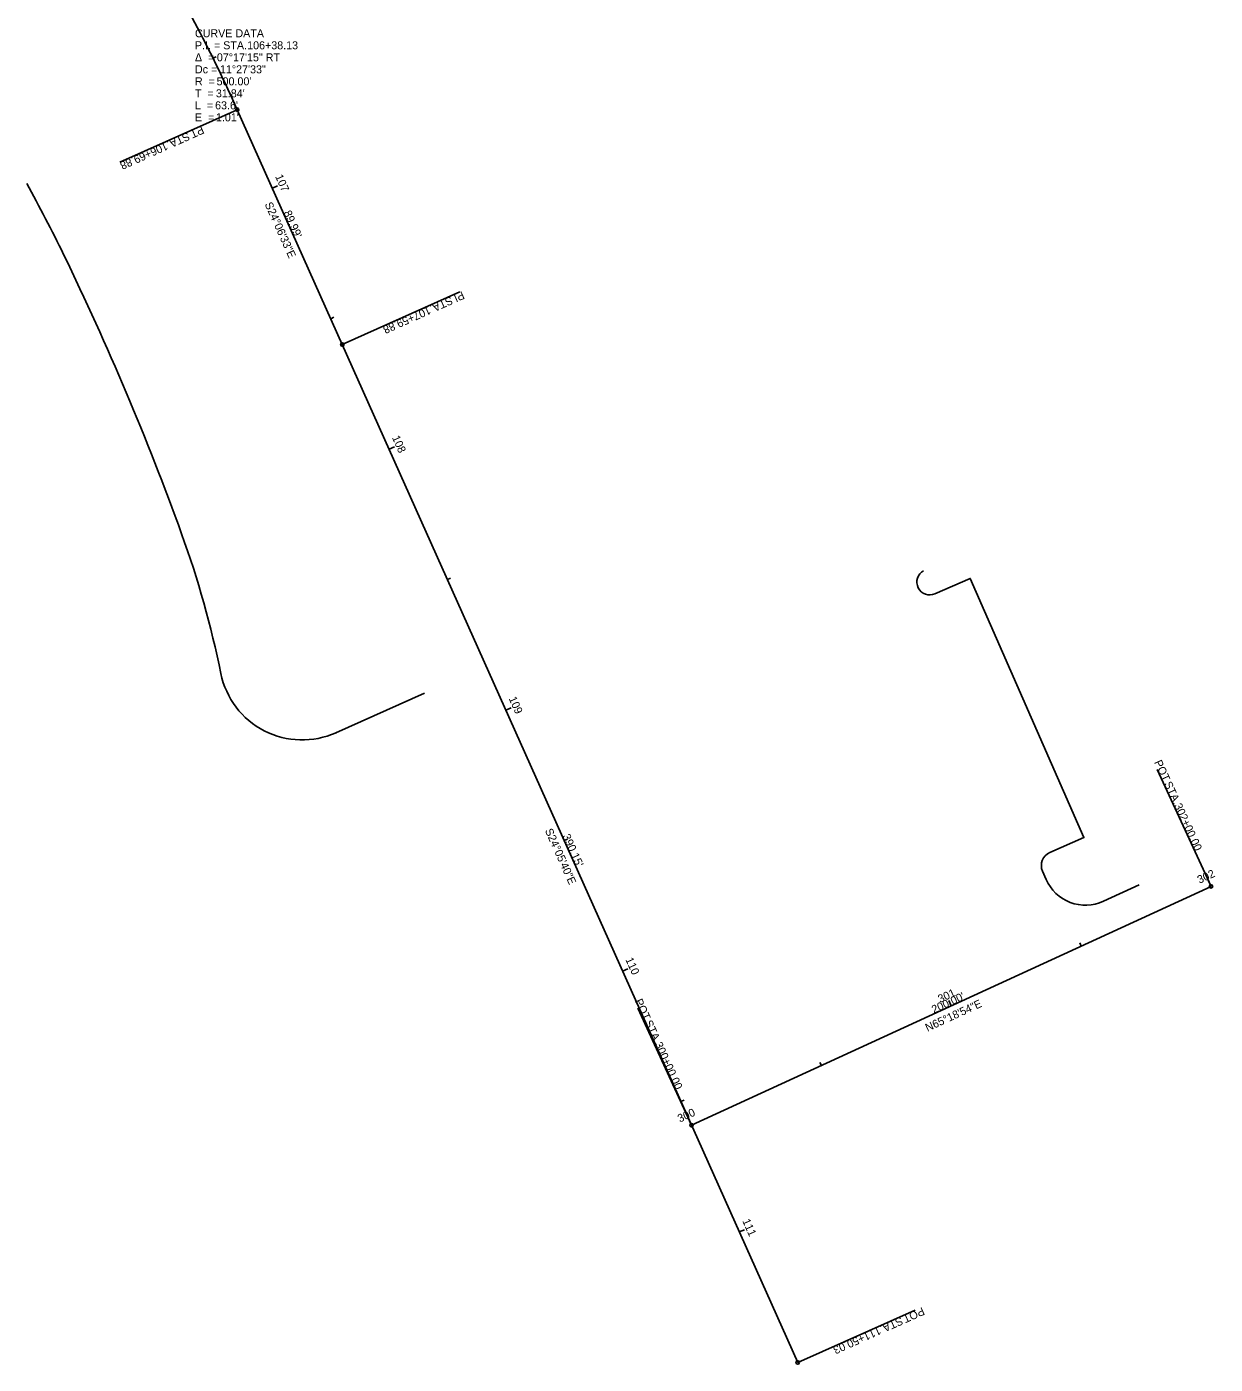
# Model space of a CAD drawing. Extents: x 1584180 to 1585753, y 271314 to 274821.
# Drawn here: x 1584386.5 to 1584802.3, y 273753 to 274220.9 of the extents above; entities that cross this region are included whole.
import ezdxf

# ---------------------------------------------------------------- set-up
doc = ezdxf.new("R2010")
doc.units = 0
for name, color, linetype in [('GE_P_Alignment', 7, 'Continuous'), ('GE_P_Alignment_100_Bearings', 7, 'Continuous'), ('GE_P_Alignment_100_Cardinal_Points', 7, 'Continuous'), ('GE_P_Alignment_100_Curve_Data', 7, 'Continuous'), ('GE_P_Alignment_100_Distances', 7, 'Continuous'), ('GE_P_Alignment_100_Stations', 7, 'Continuous'), ('SC_Scratch1', 7, 'Continuous')]:
    doc.layers.add(name, color=color, linetype=linetype)

msp = doc.modelspace()

# ---------------------------------------------------------------- linework, layer by layer
at = {"layer": 'GE_P_Alignment'}
for p, q in [((1584460.16, 274191.88), (1584496.92, 274109.74)), ((1584496.92, 274109.74), (1584656.2, 273753.58)), ((1584619.06, 273836.62), (1584800.79, 273920.15))]:
    msp.add_line(p, q, dxfattribs=at)
msp.add_arc((1584003.78, 273987.64), 500, 24.1091, 31.3967, dxfattribs=at)
at = {"layer": 'GE_P_Alignment_100_Cardinal_Points'}
for p, q in [((1584460.16, 274191.88), (1584419.09, 274173.5)), ((1584496.92, 274109.74), (1584538, 274128.11)), ((1584800.79, 273920.15), (1584781.99, 273961.04)), ((1584619.06, 273836.62), (1584600.27, 273877.51)), ((1584656.2, 273753.58), (1584697.28, 273771.95))]:
    msp.add_line(p, q, dxfattribs=at)
for centre in [(1584460.16, 274191.88), (1584496.92, 274109.74), (1584800.79, 273920.15), (1584619.06, 273836.62), (1584656.2, 273753.58)]:
    msp.add_circle(centre, 0.6, dxfattribs=at)
at = {"layer": 'GE_P_Alignment_100_Stations'}
for p, q in [((1584451.68, 274209.86), (1584452.76, 274210.4)), ((1584472.47, 274164.39), (1584474.29, 274165.21)), ((1584492.89, 274118.75), (1584493.99, 274119.24)), ((1584513.3, 274073.11), (1584515.13, 274073.93)), ((1584533.72, 274027.47), (1584534.81, 274027.96)), ((1584554.13, 273981.82), (1584555.95, 273982.64)), ((1584574.54, 273936.18), (1584575.64, 273936.67)), ((1584800.79, 273920.15), (1584799.95, 273921.97)), ((1584755.36, 273899.27), (1584754.86, 273900.36)), ((1584594.95, 273890.54), (1584596.78, 273891.35)), ((1584709.93, 273878.39), (1584709.09, 273880.2)), ((1584664.49, 273857.5), (1584663.99, 273858.59)), ((1584615.37, 273844.89), (1584616.46, 273845.38)), ((1584619.06, 273836.62), (1584618.23, 273838.44)), ((1584635.78, 273799.25), (1584637.6, 273800.06)), ((1584656.19, 273753.6), (1584657.29, 273754.09))]:
    msp.add_line(p, q, dxfattribs=at)
at = {"layer": 'SC_Scratch1'}
for p, q in [((1584494.7, 273973.92), (1584525.72, 273987.79)), ((1584741.86, 273925.44), (1584743.13, 273922.55)), ((1584763.13, 273914.95), (1584775.71, 273920.73))]:
    msp.add_line(p, q, dxfattribs=at)
msp.add_lwpolyline([(1584704.22, 274022.5), (1584716.58, 274027.92), (1584756.34, 273937.25), (1584744.43, 273932.03)], dxfattribs=at)
for centre, radius, start, end in [((1583904.84, 273900.62), 550, 25.9426, 28.8595), ((1583500.18, 273703.76), 1000, 19.86055, 25.94259), ((1584111.52, 273924.59), 350, 11.5381, 19.8605), ((1584702.41, 274026.62), 4.5, 118.8228, 293.679), ((1584482.87, 274000.39), 29, 191.5381, 294.0946), ((1584746.44, 273927.45), 5, 113.679, 203.6762), ((1584756.87, 273928.58), 15, 203.679, 294.685)]:
    msp.add_arc(centre, radius, start, end, dxfattribs=at)

# ---------------------------------------------------------------- texts
at = {"layer": 'GE_P_Alignment_100_Bearings'}
for s, rotation, p in [('S24°06\'33"E', 294.1091, (1584469.69, 274158.83)), ('S24°05\'40"E', 294.0946, (1584567.72, 273939.68)), ('N65°18\'54"E', 24.685, (1584701.61, 273869.28))]:
    msp.add_text(s, height=2.8, rotation=rotation, dxfattribs=at).set_placement(p)
at = {"layer": 'GE_P_Alignment_100_Cardinal_Points'}
for s, rotation, p in [('PT', 204.1091, (1584447.76, 274186.29)), (' STA. ', 204.1091, (1584443.73, 274184.48)), ('106+69.88', 204.1091, (1584435.11, 274180.62)), (' STA. ', 204.0946, (1584535.73, 274127.05)), ('PI', 204.0946, (1584538.83, 274128.43)), ('107+59.88', 204.0946, (1584527.1, 274123.19)), ('POT', 294.685, (1584780.86, 273963.6)), (' STA. ', 294.685, (1584783.87, 273957.05)), ('302+00.00', 294.685, (1584787.82, 273948.47)), ('POT', 294.685, (1584599.14, 273880.07)), (' STA. ', 294.685, (1584602.15, 273873.53)), ('300+00.00', 294.685, (1584606.09, 273864.94)), (' STA. ', 204.0946, (1584693.21, 273770.08)), ('POT', 204.0946, (1584699.78, 273773.02)), ('111+50.03', 204.0946, (1584684.58, 273766.23))]:
    msp.add_text(s, height=2.8, rotation=rotation, dxfattribs=at).set_placement(p)
at = {"layer": 'GE_P_Alignment_100_Curve_Data'}
for s, p in [('CURVE DATA', (1584445.37, 274217.2)), ('P.I. = STA. ', (1584445.37, 274213)), ('106+38.13', (1584463.63, 274213)), ('Δ  = ', (1584445.37, 274208.8)), ('07°17\'15" RT', (1584453.04, 274208.8)), ('Dc = ', (1584445.37, 274204.6)), ('11°27\'33"', (1584454.11, 274204.6)), ('R  = ', (1584445.37, 274200.4)), ("500.00'", (1584452.95, 274200.4)), ('T  = ', (1584445.37, 274196.2)), ("31.84'", (1584452.7, 274196.2)), ('L  = ', (1584445.37, 274192)), ('E  = ', (1584445.37, 274187.8)), ("63.6'", (1584452.41, 274192)), ("1.01'", (1584452.71, 274187.8))]:
    msp.add_text(s, height=2.8, dxfattribs=at).set_placement(p)
at = {"layer": 'GE_P_Alignment_100_Distances'}
for s, rotation, p in [("89.99'", 294.1091, (1584476.31, 274155.9)), ("390.15'", 294.0946, (1584573.87, 273937.77)), ("200.00'", 24.685, (1584703.84, 273875.63))]:
    msp.add_text(s, height=2.8, rotation=rotation, dxfattribs=at).set_placement(p)
at = {"layer": 'GE_P_Alignment_100_Stations'}
for s, rotation, p in [('107', 294.1091, (1584473.35, 274168.53)), ('108', 294.0946, (1584514.23, 274077.18)), ('109', 294.0946, (1584555.06, 273985.87)), ('302', 24.685, (1584796.76, 273921.05)), ('110', 294.0946, (1584595.87, 273894.61)), ('301', 24.685, (1584706.02, 273879.34)), ('300', 24.685, (1584614.98, 273837.5)), ('111', 294.0946, (1584636.77, 273803.15))]:
    msp.add_text(s, height=2.8, rotation=rotation, dxfattribs=at).set_placement(p)

doc.saveas('drawing.dxf')
